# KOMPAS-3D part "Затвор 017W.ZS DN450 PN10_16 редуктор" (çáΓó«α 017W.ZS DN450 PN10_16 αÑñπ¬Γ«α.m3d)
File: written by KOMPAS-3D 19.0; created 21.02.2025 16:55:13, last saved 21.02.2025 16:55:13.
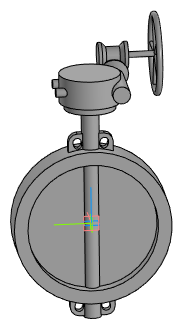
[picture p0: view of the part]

Document properties: Автор: Евгений; Полное имя файла: Затвор 017W.ZS DN450 PN10_16 редуктор.a3d

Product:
- Part/product: Затвор 017W.ZS DN450 PN10_16 редуктор
    Масса: 146.259

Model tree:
1. Операция без истории:1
